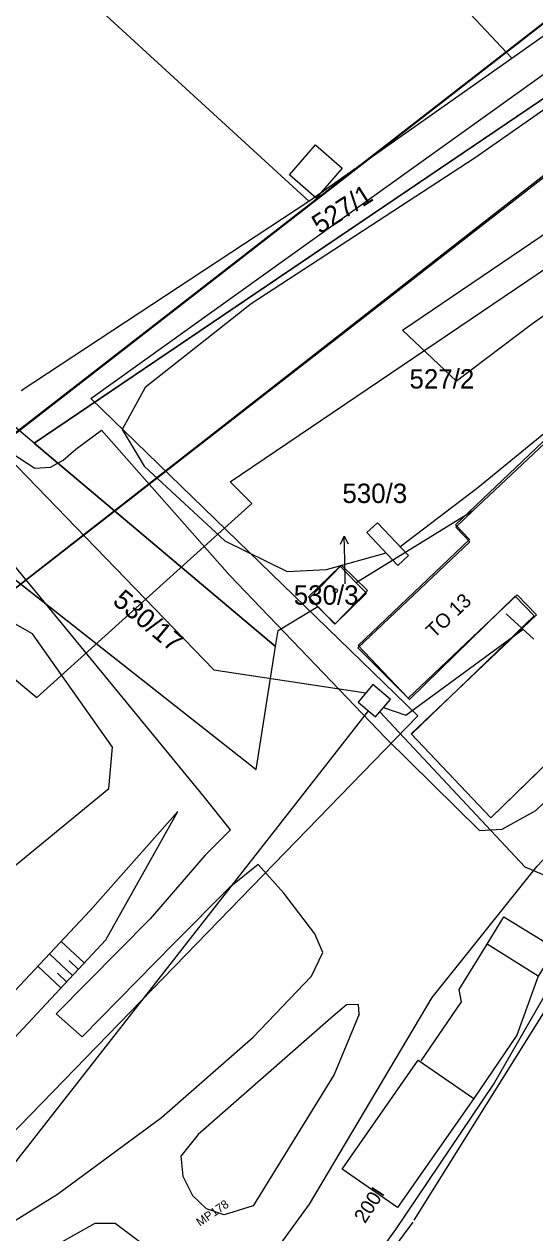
# Model space of a CAD drawing. Extents: x -469926 to -462499, y -1098642 to -1092733.
# Drawn here: x -467694.8 to -467650, y -1096936.1 to -1096830 of the extents above; entities that cross this region are included whole.
import ezdxf

# ---------------------------------------------------------------- set-up
doc = ezdxf.new("R2010")
doc.units = 0
for name, color, linetype in [('Vrstva 1', 7, 'Continuous'), ('Vrstva 11', 7, 'Continuous'), ('Vrstva 12', 7, 'Continuous'), ('Vrstva 13', 7, 'Continuous'), ('Vrstva 14', 7, 'Continuous'), ('Vrstva 16', 7, 'Continuous'), ('Vrstva 17', 7, 'Continuous'), ('Vrstva 25', 7, 'Continuous'), ('Vrstva 42', 7, 'Continuous'), ('Vrstva 44', 7, 'Continuous'), ('Vrstva 48', 7, 'Continuous'), ('Vrstva 50', 7, 'Continuous'), ('Vrstva 51', 7, 'Continuous'), ('Vrstva 52', 7, 'Continuous'), ('Vrstva 6', 7, 'Continuous'), ('Vrstva 62', 7, 'Continuous'), ('Vrstva 7', 7, 'Continuous')]:
    doc.layers.add(name, color=color, linetype=linetype)

msp = doc.modelspace()

# ---------------------------------------------------------------- linework, layer by layer
at = {"layer": 'Vrstva 1'}
for p, q in [((-467678.06, -1096805.05), (-467651.98, -1096833)), ((-467669.8, -1096845.56), (-467694.53, -1096822.88)), ((-467651.98, -1096833), (-467647.58, -1096829.89)), ((-467643.65, -1096832.79), (-467693.92, -1096866.8)), ((-467669.8, -1096845.56), (-467651.98, -1096833)), ((-467695.05, -1096862.18), (-467669.8, -1096845.56)), ((-467693.92, -1096866.8), (-467697.54, -1096863.73)), ((-467693.92, -1096866.8), (-467672.71, -1096884.64)), ((-467648.61, -1096866.35), (-467655.43, -1096872.78)), ((-467655.43, -1096872.78), (-467665.63, -1096879.05)), ((-467655.43, -1096872.78), (-467656.89, -1096874.17)), ((-467656.89, -1096874.17), (-467655.66, -1096875.47)), ((-467655.66, -1096875.47), (-467665.5, -1096884.77)), ((-467698.99, -1096876.13), (-467674.43, -1096895.44)), ((-467667.04, -1096877.59), (-467669.84, -1096880.28)), ((-467665.63, -1096879.05), (-467667.04, -1096877.59)), ((-467667.52, -1096882.68), (-467664.74, -1096879.98)), ((-467664.74, -1096879.98), (-467665.63, -1096879.05)), ((-467672.49, -1096883.26), (-467669.02, -1096881.13)), ((-467669.84, -1096880.28), (-467669.02, -1096881.13)), ((-467669.02, -1096881.13), (-467667.52, -1096882.68)), ((-467660.97, -1096889.3), (-467651.69, -1096880.23)), ((-467651.69, -1096880.23), (-467650.01, -1096881.96)), ((-467650.01, -1096881.96), (-467660.78, -1096892.36)), ((-467672.71, -1096884.64), (-467672.49, -1096883.26)), ((-467674.43, -1096895.44), (-467672.71, -1096884.64)), ((-467672.91, -1096884.47), (-467672.71, -1096884.64)), ((-467665.5, -1096884.77), (-467660.97, -1096889.3)), ((-467653.82, -1096899.69), (-467639.11, -1096885.4)), ((-467660.78, -1096892.36), (-467653.82, -1096899.69))]:
    msp.add_line(p, q, dxfattribs=at)
at = {"layer": 'Vrstva 11'}
for points in [[(-467672.71, -1096884.64), (-467693.92, -1096866.8), (-467643.65, -1096832.79), (-467625.54, -1096846.08), (-467581.4, -1096811.95)], [(-467888.22, -1097049.59), (-467816.34, -1096983.49), (-467791.5, -1097010.1), (-467774.92, -1096994.74), (-467799.69, -1096968.2), (-467698.99, -1096876.13), (-467674.43, -1096895.44), (-467672.71, -1096884.64)]]:
    msp.add_lwpolyline(points, dxfattribs=at)
at = {"layer": 'Vrstva 12'}
for p, q in [((-467703.89, -1096872.43), (-467592.84, -1096786.13)), ((-467786, -1096949.88), (-467614.04, -1096816.09))]:
    msp.add_line(p, q, dxfattribs=at)
for points in [[(-467659.93, -1096921.03), (-467656.39, -1096915.84), (-467656.59, -1096914.77), (-467654.15, -1096910.79)], [(-467649.65, -1096913.6), (-467651.54, -1096918.78), (-467655.32, -1096924.33)]]:
    msp.add_lwpolyline(points, dxfattribs=at)
at = {"layer": 'Vrstva 13'}
for points in [[(-467727.78, -1096843.73), (-467705.29, -1096862.13), (-467701.24, -1096864.76), (-467697.17, -1096866.85), (-467693.86, -1096868.99), (-467692.49, -1096868.91), (-467691.37, -1096868.3), (-467690.25, -1096867.33), (-467688.01, -1096865.65), (-467676.72, -1096878.43), (-467663.03, -1096892.69), (-467654.8, -1096900.8), (-467652.82, -1096900.68), (-467649.88, -1096899.05), (-467645.62, -1096894.97), (-467638.97, -1096887.39), (-467637.19, -1096884.23), (-467637.21, -1096882.45)], [(-467704.88, -1096983.2), (-467697.29, -1096972.53), (-467683.76, -1096952.91), (-467669.75, -1096933.63), (-467658.97, -1096915.46), (-467649.74, -1096903.94), (-467641.34, -1096894.98), (-467634.59, -1096886.79), (-467627.62, -1096876.3), (-467620.64, -1096867.78), (-467608.23, -1096855.59)], [(-467678.91, -1096902.98), (-467676.68, -1096900.74), (-467678.98, -1096897.86), (-467693.29, -1096880.42), (-467700.73, -1096871.38), (-467702.35, -1096870.56), (-467703.98, -1096870.45), (-467707.26, -1096872.8), (-467727.88, -1096891.41), (-467756.36, -1096917.49), (-467788.52, -1096947.03), (-467806.6, -1096963.7), (-467824.65, -1096980.62), (-467843.3, -1096999), (-467866.12, -1097022.61), (-467884.33, -1097042.53), (-467892.61, -1097052.34), (-467897.89, -1097060.51), (-467900, -1097063.45)], [(-467678.91, -1096902.98), (-467683.74, -1096908.55), (-467691.97, -1096916.91), (-467689.71, -1096918.91), (-467681.65, -1096910.74), (-467676.79, -1096905.84)], [(-467706.56, -1096941.13), (-467699.06, -1096937.19), (-467691.85, -1096932.73), (-467682.72, -1096926.01), (-467674.67, -1096918.96), (-467669.57, -1096913.61), (-467668.56, -1096911.51), (-467669.27, -1096909.87), (-467671.99, -1096906.32), (-467674.25, -1096903.79), (-467676.79, -1096905.84)], [(-467665.37, -1096916.94), (-467665.45, -1096916.08), (-467666.49, -1096916.12), (-467667.88, -1096917.27), (-467679.52, -1096927.51), (-467681.03, -1096929.39), (-467680.85, -1096931.15), (-467680.01, -1096932.85)], [(-467665.37, -1096916.94), (-467667.56, -1096922.24), (-467674.69, -1096933.76), (-467677.23, -1096934.56), (-467678.79, -1096934.02), (-467680.01, -1096932.85)], [(-467684.24, -1096937.24), (-467686.8, -1096935.32), (-467688.58, -1096935.32), (-467693.59, -1096938.13), (-467706.05, -1096944.75)]]:
    msp.add_lwpolyline(points, dxfattribs=at)
at = {"layer": 'Vrstva 14'}
for points in [[(-467860.1, -1097000.39), (-467842.55, -1096988.89), (-467703.81, -1096872.23), (-467592.76, -1096786.04), (-467500.12, -1096696)], [(-467838.63, -1097000.12), (-467786.77, -1096950.75), (-467613.45, -1096815.34), (-467500.17, -1096715.8)]]:
    msp.add_lwpolyline(points, dxfattribs=at)
msp.add_lwpolyline([(-467671.49, -1096843.24), (-467669.21, -1096840.61), (-467666.86, -1096842.65), (-467669.14, -1096845.28)], close=True, dxfattribs=at)
at = {"layer": 'Vrstva 16'}
for p, q in [((-467666.65, -1096877.06), (-467666.7, -1096874.96)), ((-467666.61, -1096879.16), (-467666.65, -1096877.06))]:
    msp.add_line(p, q, dxfattribs=at)
msp.add_lwpolyline([(-467667.03, -1096875.67), (-467666.7, -1096874.96), (-467666.33, -1096875.65)], dxfattribs=at)
at = {"layer": 'Vrstva 25'}
msp.add_circle((-467667.46, -1096879.75), 0.175, dxfattribs=at)
at = {"layer": 'Vrstva 42'}
for p, q in [((-467701.56, -1096862.5), (-467678.14, -1096886.7)), ((-467652.48, -1096881.77), (-467650.03, -1096884)), ((-467661.27, -1096890.69), (-467650.98, -1096883.13)), ((-467678.14, -1096886.7), (-467664.78, -1096888.73)), ((-467664.17, -1096888), (-467665.46, -1096889.53)), ((-467662.64, -1096889.29), (-467664.17, -1096888)), ((-467665.46, -1096889.53), (-467663.93, -1096890.82)), ((-467663.93, -1096890.82), (-467662.64, -1096889.29)), ((-467664.57, -1096890.28), (-467732.82, -1096977.49)), ((-467663.56, -1096890.39), (-467650.83, -1096904.01)), ((-467663.23, -1096890), (-467661.27, -1096890.69)), ((-467650.83, -1096904.01), (-467547.08, -1096947.85))]:
    msp.add_line(p, q, dxfattribs=at)
at = {"layer": 'Vrstva 44'}
for p, q in [((-467645.3, -1096910.55), (-467660.57, -1096935.02)), ((-467660.67, -1096935.19), (-467670.15, -1096947.9))]:
    msp.add_line(p, q, dxfattribs=at)
at = {"layer": 'Vrstva 48'}
for points in [[(-467689.52, -1096912.43), (-467691.55, -1096910.54)], [(-467690.55, -1096913.53), (-467692.58, -1096911.64)], [(-467691.57, -1096914.63), (-467693.6, -1096912.73)], [(-467690.04, -1096912.98), (-467690.85, -1096912.23)], [(-467691.06, -1096914.08), (-467691.87, -1096913.32)]]:
    msp.add_lwpolyline(points, dxfattribs=at)
at = {"layer": 'Vrstva 50'}
for p, q in [((-467676.69, -1096870.2), (-467638.93, -1096844.64)), ((-467674.8, -1096872.09), (-467676.69, -1096870.2)), ((-467693.68, -1096889.14), (-467674.8, -1096872.09)), ((-467696.51, -1096886.77), (-467693.68, -1096889.14))]:
    msp.add_line(p, q, dxfattribs=at)
at = {"layer": 'Vrstva 51'}
for p, q in [((-467653.59, -1096923.12), (-467646.81, -1096911.31)), ((-467662.16, -1096935.84), (-467653.59, -1096923.12)), ((-467677.69, -1096957.14), (-467662.16, -1096935.84))]:
    msp.add_line(p, q, dxfattribs=at)
at = {"layer": 'Vrstva 52'}
for p, q in [((-467688.94, -1096862.88), (-467603.4, -1096801.61)), ((-467688.94, -1096862.88), (-467660.24, -1096890.74)), ((-467741.73, -1096974.69), (-467660.24, -1096890.74))]:
    msp.add_line(p, q, dxfattribs=at)
at = {"layer": 'Vrstva 6'}
for points in [[(-467653.82, -1096899.7), (-467639.09, -1096885.34), (-467649.09, -1096874.8), (-467644.54, -1096870.48), (-467648.67, -1096866.12), (-467656.93, -1096873.96), (-467655.69, -1096875.27), (-467665.48, -1096884.55), (-467661.07, -1096889.2), (-467651.5, -1096880.12), (-467649.82, -1096881.88), (-467660.82, -1096892.32)], [(-467661.99, -1096877.55), (-467661.06, -1096876.67), (-467663.78, -1096873.78), (-467664.71, -1096874.65)], [(-467667.49, -1096882.67), (-467664.64, -1096879.74), (-467666.92, -1096877.51), (-467669.78, -1096880.44)], [(-467654.15, -1096910.79), (-467652.67, -1096908.4), (-467648.14, -1096911.17), (-467649.65, -1096913.6)], [(-467666.86, -1096930.53), (-467660.2, -1096920.97), (-467655.32, -1096924.33), (-467662.02, -1096933.9)]]:
    msp.add_lwpolyline(points, close=True, dxfattribs=at)
at = {"layer": 'Vrstva 62'}
for points in [[(-467527.99, -1096756.99), (-467554.85, -1096773.47), (-467589.8, -1096796.24), (-467621.45, -1096818.11), (-467655.2, -1096841.73), (-467674.85, -1096854.56), (-467684.17, -1096861.9), (-467686.2, -1096865.6), (-467684.25, -1096868.82), (-467677.16, -1096875.38), (-467671.69, -1096878.07), (-467668.26, -1096877.89), (-467663.02, -1096876.44)], [(-467522.31, -1096767.41), (-467549.13, -1096785.94), (-467586.52, -1096811.96), (-467621.91, -1096836.45), (-467650.24, -1096856.38), (-467656.83, -1096861.34), (-467661.57, -1096856.87), (-467641.59, -1096843.33), (-467614.89, -1096825.18), (-467586.93, -1096805.79), (-467551.31, -1096780.81), (-467524.91, -1096761.87)], [(-467661.8, -1096875.91), (-467654.96, -1096870.7), (-467643.36, -1096861.2)], [(-467800.34, -1097003.64), (-467777.43, -1096977.88), (-467748.29, -1096949.28), (-467709.75, -1096915.5), (-467687.36, -1096897.11), (-467687.04, -1096893.5), (-467694.06, -1096883.54), (-467703.23, -1096878.37), (-467709.88, -1096880.31), (-467722.53, -1096890.42), (-467758.89, -1096921.95), (-467796.22, -1096957.64), (-467822.71, -1096988.5), (-467844.4, -1097016.47)]]:
    msp.add_lwpolyline(points, dxfattribs=at)
msp.add_lwpolyline([(-467745.51, -1096960.84), (-467744.04, -1096963.93), (-467740.82, -1096966.09), (-467738.67, -1096965.55), (-467736.39, -1096963.47), (-467725.98, -1096951.67), (-467711.49, -1096937.94), (-467699.32, -1096922.93), (-467687.62, -1096910.4), (-467681.3, -1096899.13), (-467688.99, -1096907.82), (-467701.35, -1096920.98), (-467713.26, -1096936.25), (-467727.28, -1096950.02), (-467738.92, -1096962.51), (-467740.6, -1096963.4), (-467742.43, -1096962.85)], close=True, dxfattribs=at)

# ---------------------------------------------------------------- texts
at = {"layer": 'Vrstva 11'}
msp.add_text('200I', height=1.25, rotation=56.7962, dxfattribs=at).set_placement((-467664.87, -1096935.38))
at = {"layer": 'Vrstva 17'}
msp.add_text('MP178', height=0.75, rotation=34.5693, dxfattribs=at).set_placement((-467679.36, -1096935.6))
at = {"layer": 'Vrstva 50'}
for s, rotation, p in [('527/1', 32.427, (-467668.83, -1096848.48)), ('530/17', 320.4, (-467687.11, -1096880.82))]:
    msp.add_text(s, height=1.7, rotation=rotation, dxfattribs=at).set_placement(p)
for s, p in [('527/2', (-467660.96, -1096862)), ('530/3', (-467666.85, -1096872.05)), ('530/3', (-467671.12, -1096880.98))]:
    msp.add_text(s, height=1.7, dxfattribs=at).set_placement(p)
at = {"layer": 'Vrstva 7'}
msp.add_text('TO 13', height=1.25, rotation=43.5664, dxfattribs=at).set_placement((-467658.79, -1096883.98))

doc.saveas('drawing.dxf')
